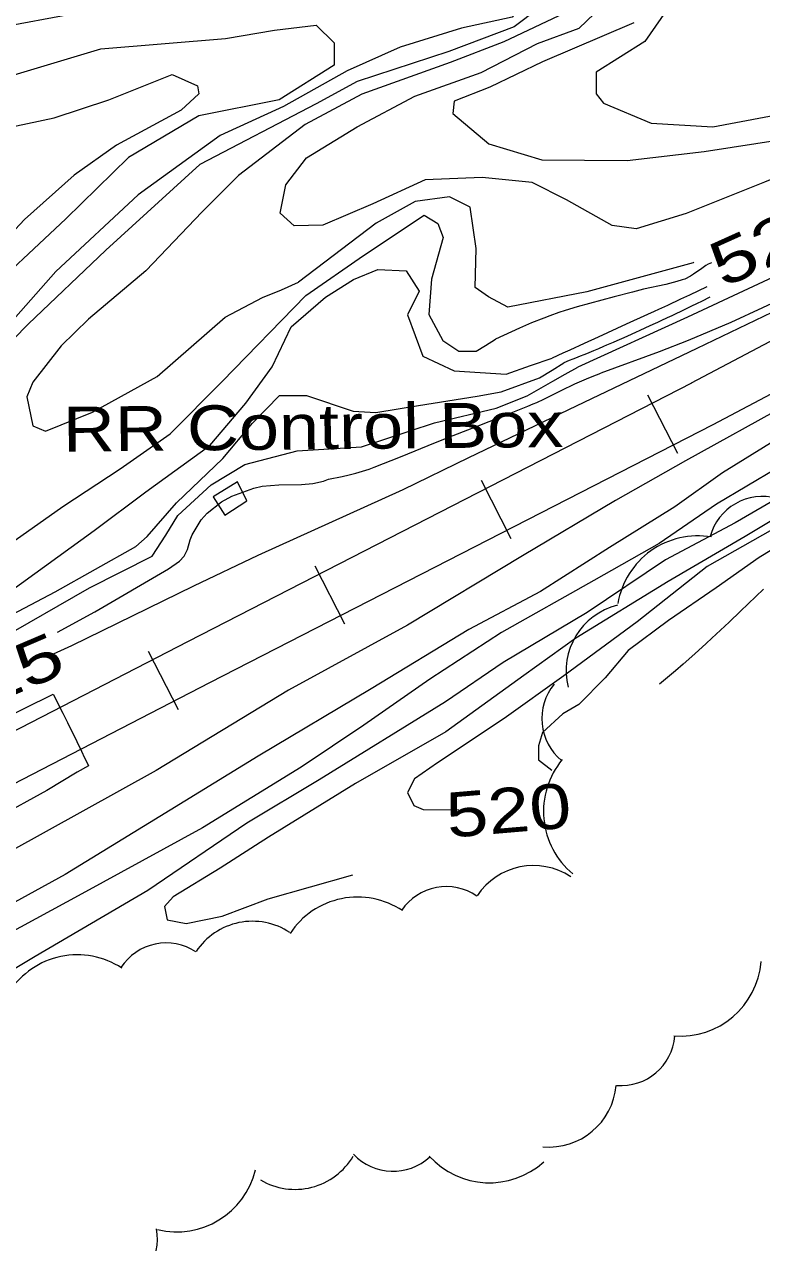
# Model space of a CAD drawing. Extents: x 2361284 to 2366480, y 6976556 to 6985346.
# Drawn here: x 2363855.4 to 2363934.2, y 6978452.5 to 6978582.8 of the extents above; entities that cross this region are included whole.
import ezdxf
from ezdxf.enums import TextEntityAlignment as Align

# ---------------------------------------------------------------- set-up
doc = ezdxf.new("R2010")
doc.units = 0
doc.header["$LTSCALE"] = 1.9
for name, color, linetype, lineweight in [('12', 7, 'Continuous', 13), ('13', 7, 'Continuous', 13), ('16', 7, 'Continuous', 13), ('29', 7, 'Continuous', 13), ('8', 7, 'Continuous', 13)]:
    doc.layers.add(name, color=color, linetype=linetype, lineweight=lineweight)

msp = doc.modelspace()

# ---------------------------------------------------------------- linework, layer by layer
at = {"layer": '12'}
for points in [[(2363912.923, 6978586.483), (2363907.74, 6978582.553), (2363900.745, 6978579.906), (2363890.955, 6978576.683), (2363886.547, 6978574.302), (2363874.108, 6978567.823), (2363864.085, 6978558.677), (2363855.779, 6978550.747), (2363844.766, 6978539.512)], [(2363858.465, 6978515.481), (2363860.437, 6978516.37), (2363873.467, 6978522.764), (2363880.346, 6978526.04), (2363895.87, 6978533.068), (2363902.879, 6978536.485), (2363914.396, 6978542.015), (2363927.278, 6978548.197), (2363938.865, 6978553.757), (2363951.101, 6978559.594), (2363969.516, 6978568.581)], [(2363850.118, 6978524.642), (2363859.476, 6978531.242), (2363865.617, 6978535.27), (2363870.952, 6978539.031), (2363876.519, 6978544.605), (2363885.452, 6978553.81), (2363891.622, 6978558.078), (2363898.091, 6978562.391), (2363899.569, 6978561.514), (2363900.154, 6978560.01), (2363898.906, 6978555.558), (2363898.592, 6978551.784), (2363900.118, 6978549.009), (2363901.82, 6978547.855), (2363903.671, 6978547.843), (2363904.675, 6978548.482), (2363905.718, 6978549.142)], [(2363973.086, 6978561.293), (2363971.165, 6978560.375), (2363968.328, 6978558.978), (2363960.139, 6978554.59), (2363954.696, 6978551.708), (2363947.939, 6978548.193), (2363937.144, 6978542.252), (2363926.053, 6978536.125), (2363918.562, 6978531.903), (2363908.628, 6978525.979), (2363896.328, 6978518.552), (2363883.593, 6978511.6), (2363869.464, 6978503.025), (2363853.755, 6978494.325), (2363837.019, 6978485.496), (2363826.789, 6978480.119), (2363815.635, 6978474.272), (2363800.544, 6978465.817), (2363786.786, 6978458.187), (2363774.828, 6978451.633)], [(2363928.822, 6978557.322), (2363928.462, 6978557.146), (2363928.23, 6978557.01), (2363927.78, 6978556.711), (2363926.896, 6978556.079), (2363926.594, 6978555.884), (2363926.44, 6978555.794), (2363926.124, 6978555.632), (2363925.961, 6978555.561), (2363925.709, 6978555.472), (2363925.124, 6978555.302), (2363924.732, 6978555.198), (2363923.944, 6978555.006), (2363921.569, 6978554.477), (2363920.782, 6978554.286), (2363920.39, 6978554.182), (2363918.417, 6978553.657), (2363915.784, 6978552.96), (2363914.473, 6978552.591), (2363913.169, 6978552.195), (2363912.521, 6978551.984), (2363911.554, 6978551.648), (2363910.891, 6978551.401), (2363909.581, 6978550.874), (2363908.286, 6978550.315), (2363907.428, 6978549.929), (2363905.718, 6978549.142)], [(2363948.892, 6978537.362), (2363947.738, 6978536.791), (2363945.253, 6978535.077), (2363941.926, 6978532.626), (2363938.058, 6978530.329), (2363928.381, 6978524.816), (2363920.895, 6978518.916), (2363913.04, 6978513.14), (2363906.674, 6978508.569), (2363899.518, 6978503.851), (2363897.084, 6978502.118), (2363896.318, 6978500.661), (2363896.991, 6978499.287), (2363898.015, 6978498.837), (2363901.797, 6978498.803)]]:
    msp.add_lwpolyline(points, dxfattribs=at)
at = {"layer": '13'}
for points in [[(2363853.955, 6978582.711), (2363864.727, 6978584.705), (2363872.269, 6978585.657), (2363886.71, 6978586.634), (2363893.458, 6978586.858), (2363901.959, 6978588.019), (2363905.064, 6978588.539), (2363907.326, 6978587.13), (2363908.537, 6978584.942), (2363907.52, 6978583.591), (2363902.112, 6978582.409), (2363895.55, 6978580.367), (2363889.874, 6978577.843), (2363883.08, 6978574.029), (2363876.299, 6978570.924), (2363867.539, 6978564.561), (2363858.737, 6978556.366), (2363849.594, 6978546.069)], [(2363926.264, 6978587.57), (2363921.715, 6978580.986), (2363916.487, 6978577.686), (2363916.488, 6978575.382), (2363917.268, 6978574.374), (2363922.369, 6978572.242), (2363928.964, 6978571.855), (2363937.498, 6978573.446), (2363945.373, 6978576.12), (2363954.736, 6978581.17), (2363961.659, 6978584.057)], [(2363973.649, 6978584.061), (2363966.031, 6978580.647), (2363957.635, 6978576.048), (2363945.807, 6978570.495), (2363934.49, 6978565.947), (2363926.122, 6978562.578), (2363920.783, 6978560.935), (2363918.213, 6978561.281), (2363913.326, 6978564.036), (2363909.658, 6978565.891), (2363904.314, 6978566.431), (2363898.225, 6978566.193), (2363892.629, 6978563.619), (2363887.261, 6978561.337), (2363884.191, 6978561.248), (2363882.698, 6978562.615), (2363883.329, 6978565.661), (2363885.542, 6978568.532), (2363890.931, 6978571.854), (2363897.12, 6978575.113), (2363904.217, 6978577.669), (2363910.227, 6978580.746), (2363914.662, 6978582.389), (2363918.715, 6978586.278)], [(2363913.793, 6978584.341), (2363906.636, 6978580.922), (2363900.876, 6978578.717), (2363891.458, 6978575.339), (2363885.378, 6978572.091), (2363878.25, 6978566.653), (2363874.367, 6978562.746), (2363868.336, 6978556.457), (2363862.205, 6978551.298), (2363859.312, 6978548.421), (2363856.278, 6978544.533), (2363855.633, 6978542.977), (2363856.272, 6978539.863), (2363857.629, 6978539.304), (2363862.65, 6978541.333), (2363869.574, 6978545.139), (2363876.814, 6978551.497), (2363880.824, 6978553.586), (2363882.866, 6978554.415), (2363884.658, 6978555.242)], [(2363920.516, 6978582.974), (2363910.776, 6978578.792), (2363905.112, 6978576.078), (2363901.316, 6978574.612), (2363901.167, 6978573.274), (2363905.03, 6978570.027), (2363910.685, 6978568.311), (2363919.826, 6978568.238), (2363928.048, 6978569.226), (2363936.545, 6978570.527), (2363944.881, 6978574.167), (2363954.351, 6978578.596), (2363960.404, 6978581.373), (2363967.843, 6978583.634)], [(2363851.742, 6978576.65), (2363863.54, 6978580.202), (2363876.86, 6978581.299), (2363882.122, 6978582.199), (2363886.557, 6978582.711), (2363888.475, 6978580.84), (2363888.468, 6978578.439), (2363882.603, 6978574.724), (2363874.019, 6978573.033), (2363866.501, 6978568.571), (2363859.793, 6978562.017), (2363850.109, 6978552.964)], [(2363983.473, 6978580.593), (2363980.602, 6978578.375), (2363979.073, 6978577.411), (2363969.085, 6978571.937), (2363959.682, 6978566.877), (2363956.164, 6978565.26), (2363951.367, 6978563.33), (2363949.005, 6978562.285), (2363939.229, 6978557.541), (2363926.247, 6978551.487), (2363914.526, 6978546.157)], [(2363984.524, 6978579.453), (2363978.112, 6978575.443), (2363972.744, 6978572.101), (2363970.008, 6978570.515), (2363965.425, 6978568.068), (2363956.165, 6978563.363), (2363941.007, 6978555.688), (2363937.665, 6978554.05), (2363930.903, 6978550.932), (2363926.318, 6978548.985), (2363923.229, 6978547.773), (2363916.982, 6978545.51)], [(2363852.83, 6978571.611), (2363858.53, 6978572.806), (2363864.392, 6978574.731), (2363871.177, 6978577.435), (2363873.878, 6978576.251), (2363874.031, 6978575.372), (2363872.143, 6978573.625), (2363865.218, 6978569.899), (2363860.699, 6978566.686), (2363855.362, 6978561.945), (2363853.432, 6978559.835)], [(2363926.931, 6978557.364), (2363926.852, 6978557.323), (2363915.51, 6978554.195), (2363907.065, 6978552.555), (2363904.995, 6978553.655), (2363903.576, 6978554.652), (2363903.666, 6978558.823), (2363903.024, 6978563.248), (2363900.813, 6978564.357), (2363897.157, 6978563.862), (2363892.969, 6978561.561), (2363884.658, 6978555.242)], [(2363851.13, 6978520.232), (2363862.84, 6978528.683), (2363868.341, 6978532.806), (2363875.174, 6978537.781), (2363879.052, 6978542.309), (2363881.844, 6978546.196), (2363883.904, 6978550.455), (2363887.544, 6978553.639), (2363890.566, 6978555.528), (2363893.146, 6978556.593), (2363896.197, 6978556.462), (2363897.568, 6978554.275), (2363896.332, 6978551.743), (2363897.964, 6978547.339), (2363901.31, 6978545.751), (2363906.874, 6978545.394), (2363909.484, 6978546.319), (2363911.797, 6978547.121)], [(2363928.346, 6978554.737), (2363926.463, 6978553.855), (2363925.521, 6978553.415), (2363924.107, 6978552.757), (2363923.164, 6978552.32), (2363922.692, 6978552.102), (2363921.983, 6978551.777), (2363919.721, 6978550.739), (2363916.704, 6978549.356), (2363915.196, 6978548.666), (2363913.686, 6978547.978), (2363912.931, 6978547.634), (2363911.797, 6978547.121)], [(2363928.657, 6978553.62), (2363927.756, 6978553.178), (2363927.306, 6978552.958), (2363926.629, 6978552.629), (2363925.612, 6978552.14), (2363924.934, 6978551.815), (2363924.594, 6978551.654), (2363924.084, 6978551.412), (2363923.403, 6978551.093), (2363923.063, 6978550.933), (2363922.551, 6978550.696), (2363921.782, 6978550.342), (2363921.098, 6978550.03), (2363920.756, 6978549.875), (2363920.241, 6978549.643), (2363919.468, 6978549.299), (2363918.693, 6978548.959), (2363918.306, 6978548.79), (2363917.615, 6978548.492), (2363917.269, 6978548.344), (2363916.749, 6978548.124), (2363916.229, 6978547.906), (2363915.968, 6978547.797), (2363915.447, 6978547.582), (2363915.186, 6978547.475), (2363914.793, 6978547.315), (2363914.27, 6978547.105), (2363914.007, 6978547), (2363913.614, 6978546.844), (2363913.022, 6978546.612)], [(2363848.801, 6978516.939), (2363858.662, 6978522.113), (2363867.277, 6978526.956), (2363868.476, 6978528.047), (2363871.622, 6978531.647), (2363876.567, 6978536.384), (2363879.742, 6978540.156), (2363882.634, 6978543.113), (2363885.524, 6978543.131), (2363890.52, 6978541.458), (2363892.951, 6978541.311), (2363897.505, 6978542.045), (2363903.776, 6978543.034), (2363906.352, 6978543.509), (2363910.437, 6978545.018), (2363911.809, 6978545.841), (2363913.022, 6978546.612)], [(2363852.48, 6978516.914), (2363862.318, 6978522.548), (2363869.026, 6978525.932), (2363870.485, 6978528.166), (2363871.755, 6978530.298), (2363875.324, 6978533.582), (2363878.944, 6978535.737), (2363884.53, 6978537.2), (2363891.416, 6978537.616), (2363899.222, 6978540.191), (2363905.808, 6978541.774), (2363909.105, 6978543.065), (2363911.88, 6978544.661), (2363913.173, 6978545.414), (2363914.526, 6978546.157)], [(2363887.889, 6978534.172), (2363889.356, 6978534.471), (2363890.083, 6978534.634), (2363890.805, 6978534.813), (2363891.163, 6978534.91), (2363891.873, 6978535.125), (2363892.224, 6978535.244), (2363892.747, 6978535.438), (2363895.574, 6978536.567), (2363899.333, 6978538.087), (2363901.216, 6978538.839), (2363903.877, 6978539.882), (2363907.426, 6978541.27), (2363909.196, 6978541.976), (2363909.767, 6978542.216), (2363910.143, 6978542.385), (2363910.89, 6978542.738), (2363913.11, 6978543.841), (2363913.856, 6978544.195), (2363914.233, 6978544.364), (2363915.449, 6978544.887), (2363916.06, 6978545.14), (2363916.982, 6978545.51)], [(2363938.326, 6978540.023), (2363935.592, 6978538.306), (2363930.015, 6978534.852), (2363924.89, 6978531.204), (2363917.93, 6978526.867), (2363910.544, 6978522.157), (2363902.893, 6978518.095), (2363892.432, 6978511.734), (2363880.36, 6978504.549), (2363870.965, 6978498.789), (2363859.74, 6978491.881), (2363846.399, 6978484.575), (2363833.293, 6978477.66), (2363824.923, 6978473.38), (2363815.189, 6978468.587), (2363806.223, 6978463.801), (2363792.995, 6978456.276), (2363780.704, 6978448.928), (2363770.41, 6978442.94), (2363755.62, 6978435.549), (2363749.887, 6978432.635), (2363737.5, 6978425.986), (2363727.969, 6978420.785)], [(2363943.016, 6978538.986), (2363940.129, 6978537.569), (2363935.84, 6978535.338), (2363929.377, 6978531.496), (2363923.236, 6978527.278), (2363916.253, 6978523.331), (2363906.377, 6978517.788), (2363898.713, 6978512.774), (2363891.669, 6978507.847), (2363884.942, 6978503.362), (2363874.393, 6978496.882), (2363861.49, 6978489.809), (2363850.008, 6978483.589), (2363838.37, 6978477.018), (2363825.948, 6978469.759), (2363816.852, 6978465.172), (2363806.834, 6978460.588), (2363794.135, 6978454.247), (2363784.849, 6978449.407)], [(2363945.128, 6978537.646), (2363942.384, 6978536.04), (2363938.665, 6978533.755), (2363931.346, 6978529.505), (2363923.894, 6978525.534), (2363915.546, 6978519.914), (2363906.547, 6978514.558), (2363900.396, 6978510.35), (2363886.894, 6978502.031), (2363879.149, 6978497.397), (2363868.546, 6978490.186), (2363856.522, 6978483.141), (2363846.36, 6978477.054)], [(2363947.72, 6978537.591), (2363944.558, 6978535.631), (2363940.285, 6978532.75), (2363932.43, 6978528.025), (2363924.186, 6978523.226), (2363914.312, 6978517.172), (2363908.749, 6978513.179), (2363900.426, 6978507.15), (2363890.759, 6978501.608), (2363881.463, 6978495.899), (2363876.284, 6978492.579), (2363871.263, 6978489.492), (2363870.343, 6978488.463), (2363870.616, 6978487.036), (2363872.67, 6978486.645), (2363876.523, 6978487.442), (2363881.445, 6978489.299), (2363890.472, 6978491.844)], [(2363951.629, 6978536.678), (2363948.544, 6978535.129), (2363943.442, 6978531.96), (2363939.519, 6978529.173), (2363933.912, 6978525.779), (2363929.312, 6978522.565), (2363924.235, 6978519.058), (2363919.934, 6978515.866), (2363917.462, 6978512.932), (2363914.629, 6978510.085), (2363912.949, 6978509.089), (2363910.748, 6978507.078), (2363910.321, 6978505.644), (2363910.315, 6978504.144), (2363911.746, 6978503.047)], [(2363858.893, 6978517.796), (2363862.902, 6978519.977), (2363870.789, 6978524.589), (2363871.947, 6978525.409), (2363872.447, 6978525.925), (2363872.817, 6978526.642), (2363873.094, 6978527.701), (2363873.295, 6978528.203), (2363874.26, 6978529.808), (2363874.903, 6978530.538), (2363876.441, 6978531.735), (2363877.543, 6978532.342), (2363879.898, 6978533.216), (2363880.776, 6978533.411), (2363882.578, 6978533.563), (2363885, 6978533.607), (2363886.186, 6978533.714), (2363887.334, 6978533.968), (2363887.889, 6978534.172)], [(2363934.374, 6978522.413), (2363931.941, 6978520.062), (2363930.72, 6978518.893), (2363928.874, 6978517.151), (2363928.267, 6978516.589), (2363927.039, 6978515.479), (2363925.798, 6978514.386), (2363924.963, 6978513.665), (2363923.28, 6978512.237)], [(2363717.381, 6978443.516), (2363748.62, 6978458.614), (2363758.682, 6978463.699), (2363771.503, 6978468.931), (2363786.168, 6978475.862), (2363796.63, 6978480.922), (2363810.777, 6978487.667), (2363833.093, 6978498.669), (2363858.436, 6978511.171)], [(2363858.436, 6978511.171), (2363858.894, 6978510.28), (2363859.121, 6978509.833), (2363859.461, 6978509.163), (2363859.798, 6978508.491), (2363859.965, 6978508.155), (2363860.416, 6978507.243), (2363860.64, 6978506.787), (2363860.976, 6978506.102), (2363861.476, 6978505.073), (2363861.807, 6978504.386), (2363861.972, 6978504.042), (2363862.219, 6978503.526)], [(2363862.219, 6978503.526), (2363861.005, 6978502.855), (2363857.754, 6978500.884), (2363852.421, 6978497.953), (2363846.761, 6978494.808), (2363836.258, 6978488.749), (2363826.877, 6978483.5), (2363814.235, 6978476.369), (2363806.495, 6978472.014), (2363792.684, 6978464.783), (2363772.744, 6978454.123), (2363756.802, 6978445.781), (2363745.079, 6978439.669), (2363728.597, 6978430.493)]]:
    msp.add_lwpolyline(points, dxfattribs=at)
at = {"layer": '16'}
for centre, radius, start, end in [((2363934.27, 6978526.537), 5.78, 74.85037, 164.85037), ((2363927.372, 6978519.434), 8.675, 80.3934, 170.3934), ((2363920.519, 6978513.67), 7.233, 103.92582, 193.92582), ((2363916.461, 6978508.546), 5.78, 140.37529, 230.37529), ((2363919.541, 6978498.643), 8.675, 140.37529, 230.37529), ((2363909.79, 6978485.617), 7.233, 56.47074, 146.47074), ((2363900.479, 6978484.815), 5.78, 55.66292, 145.66292), ((2363890.999, 6978480.805), 8.675, 56.49009, 146.49009), ((2363879.748, 6978479.656), 7.233, 56.49009, 146.49009), ((2363861.029, 6978474.63), 8.675, 56.77374, 146.77374), ((2363870.527, 6978478.794), 5.78, 56.77374, 146.77374), ((2363925.501, 6978483.294), 8.675, 265.2934, 355.2934), ((2363919.143, 6978475.1), 5.78, 265.2934, 355.2934), ((2363911.434, 6978469.976), 7.233, 264.91415, 354.91415), ((2363884.295, 6978465.456), 7.233, 239.33167, 329.33168), ((2363894.771, 6978465.932), 5.78, 223.10855, 313.10855), ((2363905.083, 6978467.598), 8.675, 222.14522, 312.14522), ((2363871.645, 6978462.349), 8.675, 256.42368, 346.42368), ((2363863.804, 6978452.856), 5.78, 281.34047, 11.34047)]:
    msp.add_arc(centre, radius, start, end, dxfattribs=at)
at = {"layer": '29'}
for p, q in [((2363921.995, 6978543.178), (2363925.185, 6978536.947)), ((2363904.202, 6978534.047), (2363907.39, 6978527.817)), ((2363886.407, 6978524.907), (2363889.606, 6978518.689)), ((2363868.603, 6978515.768), (2363871.812, 6978509.538))]:
    msp.add_line(p, q, dxfattribs=at)
for points in [[(2363926.674, 6978544.462), (2363964.107, 6978564.229), (2364001.623, 6978583.856), (2364042.853, 6978605.198), (2364084.062, 6978626.542), (2364128.694, 6978649.718), (2364173.346, 6978672.904), (2364214.057, 6978694.031), (2364254.768, 6978715.12), (2364294.894, 6978735.833), (2364335.019, 6978756.535), (2364356.186, 6978767.468), (2364377.374, 6978778.399), (2364394.91, 6978787.357), (2364412.486, 6978796.234)], [(2363929.006, 6978540.034), (2363966.429, 6978559.8), (2364003.925, 6978579.417), (2364045.145, 6978600.751), (2364086.354, 6978622.094), (2364130.996, 6978645.279), (2364175.648, 6978668.465), (2364216.349, 6978689.584), (2364257.061, 6978710.672), (2364297.185, 6978731.384), (2364337.311, 6978752.087), (2364358.478, 6978763.02), (2364379.656, 6978773.951), (2364397.172, 6978782.897), (2364414.739, 6978791.766)], [(2363150.243, 6978141.478), (2363215.533, 6978175.42), (2363280.814, 6978209.362), (2363364.405, 6978252.83), (2363447.987, 6978296.307), (2363639.63, 6978395.934), (2363729.372, 6978442.55), (2363819.144, 6978489.116), (2363872.903, 6978516.859), (2363926.724, 6978544.483)], [(2363152.546, 6978137.038), (2363217.836, 6978170.982), (2363283.117, 6978204.924), (2363366.708, 6978248.391), (2363450.289, 6978291.867), (2363546.11, 6978341.683), (2363641.932, 6978391.496), (2363731.674, 6978438.111), (2363821.437, 6978484.668), (2363875.185, 6978512.41), (2363929.006, 6978540.034)]]:
    msp.add_lwpolyline(points, dxfattribs=at)
at = {"layer": '8'}
msp.add_lwpolyline([(2363879.132, 6978531.839), (2363878.151, 6978533.879), (2363875.556, 6978532.295), (2363876.795, 6978530.306)], close=True, dxfattribs=at)

# ---------------------------------------------------------------- texts
at = {"layer": '12'}
for s, rotation, width, p in [(' 520 ', 24.273, 1.35, (2363936.618, 6978557.557)), (' 525 ', 23.116, 1.35, (2363853.419, 6978510.712)), (' 520 ', 4.857, 1.25, (2363907.337, 6978496.382))]:
    msp.add_text(s, height=4.8, rotation=rotation, dxfattribs=dict(at, width=width)).set_placement(p, align=Align.CENTER)
at = {"layer": '8', "width": 1.2}
msp.add_text('RR Control Box', height=4.799, rotation=0.545, dxfattribs=at).set_placement((2363859.5, 6978537.112))

doc.saveas('drawing.dxf')
